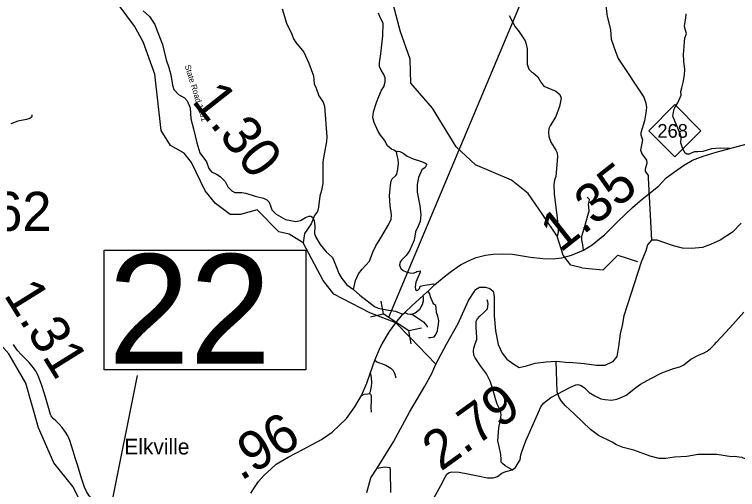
# Model space of a CAD drawing. Extents: x 1248089 to 1457196, y 820910 to 988753.
# Drawn here: x 1288997 to 1298239, y 853327 to 859401 of the extents above; entities that cross this region are included whole.
import ezdxf

# ---------------------------------------------------------------- set-up
doc = ezdxf.new("R2010")
doc.units = 0
for name, color, linetype in [('Exist Civil Demographics Community Label', 7, 'Continuous'), ('Exist Hydrographic Creek Single Shore', 7, 'Continuous'), ('Exist Hydrographic Misc Water Feature', 7, 'Continuous'), ('Exist Hydrographic River Shore', 7, 'Continuous'), ('Exist Road Non-System Type 51', 7, 'Continuous'), ('Exist Road Primary NC Attributed', 7, 'Continuous'), ('Exist Road Primary NC Shield CELL', 7, 'Continuous'), ('Exist Road Primary NC Shield Number Label', 7, 'Continuous'), ('Exist Road Primary NC Structure Culvert CELL', 7, 'Continuous'), ('Exist Road Primary NC Structure Culvert Number Label', 7, 'Continuous'), ('Exist Road Primary NC Structure Standard Bridge Number Label', 7, 'Continuous'), ('Exist Road Secondary Type 10 Attributed', 7, 'Continuous'), ('Exist Road Secondary Type 51 Attributed', 7, 'Continuous'), ('Exist Road Secondary Type 51 Label', 7, 'Continuous'), ('Prop CMT Slope Fill', 7, 'Continuous'), ('Prop GRAU CAT1 Cell', 7, 'Continuous'), ('Prop Lane Lines', 7, 'Continuous')]:
    doc.layers.add(name, color=color, linetype=linetype)

msp = doc.modelspace()

# ---------------------------------------------------------------- linework, layer by layer
at = {"layer": 'Exist Hydrographic Creek Single Shore'}
for points in [[(1293871.9, 855459.9), (1293539.5, 855586.9), (1293076.8, 855824.7), (1292941.6, 856000.6), (1292687.3, 856482.3), (1292507.4, 856594.2), (1292374.3, 856623.2), (1292097.4, 856904.5), (1291887.3, 856843), (1291754.3, 856845.7), (1291565.4, 856984.1), (1291436.3, 857147.5), (1291261.3, 857508.8), (1291164.3, 857629), (1290992.2, 857724.4), (1290871.2, 857917.2), (1290789.2, 858637.8), (1290641.3, 859051.1), (1290529.2, 859253.6), (1290335.2, 859516.8)], [(1290064.4, 852792.6), (1290015.4, 852887.3), (1289862.9, 853130), (1289742.3, 853366.9), (1289499.3, 853667.3), (1289302.3, 854114.4), (1289141.3, 854685.5), (1288925.3, 855064.1), (1288789.3, 855212.9), (1288651.5, 855179.3), (1288449.3, 855034.3), (1288244.3, 854838.1), (1288177.3, 854806.7), (1288102.3, 854818), (1287963.3, 854945.5), (1287810.2, 855175.1), (1287422.3, 855983.9), (1287286.2, 856564.4), (1287261.2, 856581.3), (1287171.2, 856993.4), (1286998.2, 857062.6), (1286909.2, 857172.7), (1286855.2, 857341.2), (1286814.2, 857384.7)], [(1294384.6, 854929.6), (1294053.9, 855270.9), (1293871.9, 855459.9)]]:
    msp.add_lwpolyline(points, dxfattribs=at)
at = {"layer": 'Exist Hydrographic Misc Water Feature'}
for points in [[(1296249.4, 856161.3), (1296108.4, 856197), (1296011.4, 856323.7), (1295933.4, 856568.2), (1295748.4, 856841.1), (1295563.4, 857110.7), (1295350.4, 857282.4), (1294888.3, 857478.8), (1294644.3, 857710.2), (1294339.3, 858202.1), (1294063.3, 858522.8), (1294054.3, 858831.6), (1293929.3, 859178.8), (1293838.3, 859531.8), (1293751.3, 859740.4)], [(1296542.7, 859616.6), (1296574.8, 859375.5), (1296614.8, 859210.6), (1296625.7, 859086.4), (1296677.9, 858928.6), (1296713.6, 858837.6), (1297039.9, 858343.6), (1297068, 858266.7), (1297074.6, 858210.7), (1297068.9, 858142.8), (1297050.4, 858043), (1297004.6, 857888), (1297003.9, 857860.1), (1297022.4, 857799.8), (1296997.1, 857664.1), (1297016.1, 857619.4), (1297074, 857537.8), (1297081.2, 857498.3), (1297057.3, 857422.4), (1297056.7, 857398.6), (1297095.2, 857341.2), (1297098.6, 857313.3), (1297140.1, 856517.1)], [(1292420.4, 859472), (1292475.8, 859287.8), (1292542.6, 859150.3), (1292565, 859089.9), (1292591.9, 859040.9), (1292694.9, 858918.2), (1292759.5, 858779.1), (1292817.6, 858617), (1292827.1, 858512.6), (1292853.8, 858460.4), (1292889.3, 858359.6), (1292943.4, 858278), (1292958.2, 858229.3), (1292988.6, 857834.8), (1292987.1, 857778.2), (1292950.6, 857595.1), (1292938.6, 857513.3), (1292938, 857239.2), (1292919.8, 857150.1), (1292897.9, 857078.3), (1292884.5, 856938.2), (1292871.1, 856882.7), (1292833.8, 856831.7), (1292791.2, 856724.3), (1292702, 856598.8), (1292687.3, 856482.3)], [(1295318.2, 859386.8), (1295394.7, 859244), (1295449.2, 859178.9), (1295524.4, 859065), (1295539.3, 859020.4), (1295550, 858960.3), (1295551.2, 858766.5), (1295573.5, 858701.3), (1295608.7, 858664.5), (1295628.5, 858656.7), (1295687.2, 858603), (1295723.5, 858534.1), (1295762.4, 858484.9), (1295916.9, 858419.4), (1295967.9, 858377.4), (1295982.7, 858329.5), (1295962.1, 858225.7), (1295915, 858098.6), (1295844, 857976.9), (1295829.1, 857941.1), (1295823.9, 857892.8), (1295826.7, 857841), (1295852.8, 857768.3), (1295916.5, 857666.9), (1295931.6, 857630.5), (1295938.4, 857581.9), (1295918.1, 857330.4), (1295901, 857282.3), (1295891.7, 857226.7), (1295896.6, 857102.6), (1295928, 856833.7), (1295944.8, 856669.6), (1295946.3, 856615.4), (1295933.4, 856568.2)], [(1296249.4, 856161.3), (1296520.5, 856135.9), (1296708.7, 856324.2), (1296959.5, 856242.3)], [(1298204, 853751.5), (1298163.8, 853746.5), (1297976.4, 853773.3), (1297736.1, 853773.2), (1297591.6, 853749), (1297435.2, 853742.2), (1297322.7, 853725.6), (1297238.7, 853725.7), (1297123.3, 853752.6), (1296913, 853831.5), (1296777.7, 853863), (1296692.4, 853896.7), (1296637.3, 853932.2), (1296463.4, 854017), (1296361.1, 854092.9), (1296152, 854296.6), (1296038.3, 854395.6), (1295990.5, 854455.7), (1295960.6, 854501.9), (1295933.4, 854578), (1295922.1, 854966.3)], [(1298651.7, 853526), (1298588.6, 853569.4), (1298533.4, 853600.7), (1298486.3, 853643.8), (1298415.2, 853679.5), (1298383.6, 853700.2), (1298296.3, 853738.2), (1298256, 853739.4), (1298204, 853751.5)], [(1293632.2, 853600), (1293730.5, 853618), (1293793.5, 853610.1), (1293800.4, 853561.6), (1293803.6, 853289.1)]]:
    msp.add_lwpolyline(points, dxfattribs=at)
at = {"layer": 'Exist Hydrographic River Shore'}
for points in [[(1298284.5, 856731), (1298172.8, 856618.1), (1298016.7, 856517.1), (1297892.8, 856462), (1297791.8, 856420.6), (1297649.6, 856406.8), (1297534.8, 856411.4), (1297420.1, 856443.6), (1297296.1, 856484.9), (1297213.5, 856517.1), (1297140.1, 856517.1), (1297089.6, 856457.4), (1297066.7, 856379.3), (1297007, 856232.3), (1296786.7, 855547.9), (1296763.7, 855423.9), (1296740.8, 855318.3), (1296717.8, 855157.5), (1296694.9, 855028.9), (1296639.8, 854960), (1296543.4, 854914.1), (1296437.9, 854914.1), (1296277.2, 854932.5), (1296089, 854950.8)], [(1294384.6, 854929.6), (1294517.7, 855186.8), (1294669.1, 855448.6), (1294802.2, 855742.6), (1294871.1, 855852.8), (1294889.4, 855885), (1294939.9, 855912.5), (1295017.9, 855912.5), (1295073, 855898.7), (1295114.3, 855862), (1295128.1, 855793.1), (1295128.1, 855687.5), (1295128.1, 855549.7), (1295146.5, 855356.8), (1295178.6, 855182.2), (1295229.1, 855072), (1295288.7, 854993.9), (1295380.5, 854929.6), (1295449.4, 854888.3), (1295541.2, 854906.6), (1295651.3, 854943.4), (1295793.6, 854961.7), (1295922.1, 854966.3), (1296089, 854950.8)], [(1293499.6, 853289.6), (1293550.1, 853477.9), (1293632.2, 853600), (1293843.3, 853935.3), (1294045.3, 854316.5), (1294242.7, 854647.2), (1294329.5, 854810.2), (1294384.6, 854929.6)]]:
    msp.add_lwpolyline(points, dxfattribs=at)
at = {"layer": 'Exist Road Non-System Type 51'}
for points in [[(1293878.7, 857645.1), (1293845.2, 857666.3), (1293815.2, 857678.7), (1293764, 857722.8), (1293730.4, 857786.4), (1293714.5, 857811.1), (1293677.5, 857857.1), (1293645.7, 857903), (1293592.8, 858017.8), (1293576.9, 858083.2), (1293587.5, 858157.4), (1293626.4, 858276), (1293654.6, 858353.8), (1293689.9, 858433.3), (1293716.4, 858473.9), (1293735.8, 858539.2), (1293734, 858592.2), (1293719.9, 858634.6), (1293682.9, 858689.4), (1293661.7, 858735.3), (1293661.7, 858781.2), (1293677.6, 858897.8), (1293704, 859129.2), (1293711.1, 859288.8), (1293675.8, 859354.2), (1293649.2, 859415.7)], [(1298141.3, 857687.4), (1298017.4, 857691), (1297906.2, 857684), (1297849.7, 857664.5), (1297796.7, 857648.6), (1297733.2, 857645.1), (1297687.3, 857645.1), (1297653.8, 857632.7), (1297620.2, 857613.3), (1297592, 857616.8), (1297569.1, 857627.4), (1297553.2, 857657.5), (1297532, 857708.7), (1297516.1, 857758.1), (1297517.9, 857825.3), (1297510.8, 857865.9), (1297484.3, 857924.2), (1297413.7, 858099.1), (1297419, 858152), (1297431.4, 858205), (1297475.5, 858272.2), (1297518.1, 858367.9), (1297516.3, 858415.6), (1297526.9, 858465), (1297546.3, 858530.4), (1297562.2, 858629.3), (1297567.5, 858696.4), (1297551.6, 858802.4), (1297548.1, 858889), (1297556.9, 858989.6), (1297562.2, 859049.7), (1297564, 859097.4), (1297585.1, 859158.2), (1297569.2, 859211.1), (1297562.2, 859255.3), (1297571, 859308.3), (1297576.3, 859354.2), (1297583.4, 859410.7)], [(1289216.6, 858118.8), (1289219.5, 858098.3), (1289213.7, 858086.6), (1289193.2, 858069), (1289149.3, 858060.2), (1289041.1, 858036.8), (1288950.4, 858001.7)], [(1293331.5, 855886.2), (1293354.8, 855997.7), (1293395.3, 856084.3), (1293443, 856146.1), (1293488.9, 856193.8), (1293533, 856246.8), (1293578.9, 856363.3), (1293617.7, 856442.8), (1293693.6, 856568.2), (1293771.3, 856700.7), (1293811.7, 856779.2), (1293817, 856839.2), (1293801.1, 856955.8), (1293790.5, 857088.3), (1293804.6, 857213.7), (1293811.7, 857273.7), (1293825.8, 857300.2), (1293864.6, 857335.6), (1293871.7, 857340.9), (1293885.8, 857358.5), (1293898.2, 857422.1), (1293903.5, 857496.3), (1293901.6, 857548), (1293889.3, 857599.2), (1293878.7, 857645.1)], [(1293878.7, 857645.1), (1293892.3, 857652.9), (1293924, 857651.2), (1293966.4, 857626.4), (1294015.8, 857591.1), (1294093.5, 857555.8), (1294185.3, 857524), (1294243.5, 857506.3), (1294268.2, 857488.7), (1294245.3, 857442.7), (1294202.9, 857412.7), (1294160.5, 857315.6), (1294142.9, 857229), (1294142.9, 857128.3), (1294180, 856955.2), (1294190.6, 856838.6), (1294181.7, 856753), (1294158.8, 856694.7), (1294123.5, 856622.3), (1294104.1, 856516.3), (1294047.6, 856380.3), (1294003.9, 856321.3), (1293949.2, 856264.8), (1293926.2, 856236.5), (1293917.4, 856194.1), (1293933.3, 856153.5), (1293963.3, 856127), (1294005.6, 856109.3), (1294051.5, 856097), (1294092.1, 856095.2), (1294125.7, 856105.8), (1294141.6, 856116.4), (1294183.9, 856121.7), (1294180.4, 856105.8), (1294153.9, 856038.7), (1294127.4, 855976.9), (1294116.8, 855916.8), (1294122.1, 855885), (1294131, 855872.7), (1294152.1, 855878), (1294175.1, 855895.6), (1294183.9, 855927.4), (1294243.9, 855939.8), (1294303.9, 855948.6), (1294344.5, 855957.4), (1294370, 855949.3)], [(1296269.1, 856389), (1296261, 856455.1), (1296250.4, 856518.7), (1296246.9, 856566.4), (1296282.2, 856677.6), (1296326.3, 856831.3), (1296342.2, 856889.6), (1296338.7, 856939.1), (1296335.1, 856975.2), (1296344, 857010.5), (1296347.5, 857033.5), (1296329.9, 857051.1), (1296315.7, 857067)], [(1294079.7, 855568.1), (1294120.3, 855587.6), (1294176.8, 855635.3), (1294213.9, 855691.8), (1294224.5, 855741.3), (1294226.2, 855776.6), (1294222.7, 855806.6)], [(1294289.8, 855271.4), (1294319.8, 855269.6), (1294360.4, 855280.2), (1294379.8, 855301.4), (1294402.8, 855354.4), (1294409.8, 855389.7), (1294418.6, 855437.4), (1294420.4, 855485.1), (1294406.3, 855543.4), (1294390.4, 855591.1), (1294386.9, 855651.2), (1294381.6, 855679.4), (1294358.6, 855695.3), (1294342.7, 855720.1), (1294314.5, 855790.7), (1294305.7, 855827.8), (1294284.5, 855863.1)], [(1295357.1, 853580), (1295267.7, 853631.3), (1295233, 853661.9), (1295216.7, 853678.3), (1295216.7, 853717), (1295212.6, 853774.2), (1295190.2, 853876.3), (1295173.9, 853951.8), (1295178, 854006.9), (1295186.1, 854115.1), (1295204.5, 854196.8), (1295216.8, 854281.2), (1295208.6, 854332.2), (1295184.1, 854385.3), (1295167.8, 854417.9), (1295149.5, 854473), (1295131.1, 854532.2), (1295108.7, 854624.1), (1295078.1, 854711.9), (1295029.1, 854807.8), (1294953.6, 854907.9), (1294886.3, 855009.9), (1294870.3, 855043.8), (1294862.1, 855101), (1294868.2, 855133.6), (1294884.5, 855190.8), (1294904.9, 855243.9), (1294907, 855272.4), (1294898.8, 855401), (1294898.8, 855478.6), (1294917.2, 855508.5), (1294943.7, 855543.2), (1294996.7, 855590.1), (1295041.6, 855639.1), (1295053.8, 855702.4), (1295047.7, 855728.9), (1295039.5, 855751.4)], [(1293988, 855589.3), (1294021.5, 855571.7), (1294055, 855568.1), (1294079.7, 855568.1)], [(1294079.7, 855568.1), (1294136.2, 855529.3), (1294224.5, 855469.2), (1294265.1, 855425.1), (1294275.7, 855402.1)], [(1293601.9, 854981.7), (1293630.2, 854960.2), (1293743.2, 854916.1), (1293806.7, 854879), (1293838.5, 854850.7), (1293859.6, 854803), (1293872, 854755.4)], [(1293536.7, 854554.5), (1293549.1, 854581), (1293561.4, 854642.9), (1293563.2, 854695.8), (1293559.7, 854761.2), (1293546.9, 854824.5)], [(1293430.7, 854529.9), (1293467.9, 854547.5), (1293512, 854552.8), (1293536.7, 854554.5), (1293547.3, 854547.5), (1293557.9, 854528), (1293557.9, 854473.3), (1293552.6, 854374.4), (1293554.4, 854314.3)]]:
    msp.add_lwpolyline(points, dxfattribs=at)
at = {"layer": 'Exist Road Primary NC Attributed'}
for points in [[(1293962.5, 855567.8), (1293988, 855589.3), (1294077.2, 855676.8), (1294222.7, 855806.6), (1294267.5, 855852.3), (1294284.5, 855863.1), (1294370, 855949.3), (1294509.9, 856065), (1294584.5, 856121), (1294695.9, 856198.6), (1294800.3, 856252.7), (1294899.1, 856293.8), (1295016.6, 856321.8), (1295113.6, 856334.9), (1295238.6, 856340.5), (1295361.7, 856334.9), (1295593.9, 856299.4), (1295750.6, 856278.9), (1295881.1, 856277), (1295994.9, 856290.1), (1296118, 856321.8), (1296269.1, 856389), (1296380, 856457.1), (1296544.1, 856585.9), (1296713.8, 856757.6), (1296898.4, 856935), (1296994.8, 857019.9), (1297231.7, 857212.2), (1297328.7, 857311.1), (1297462.9, 857410), (1297548.7, 857471.6), (1297662, 857538.1), (1297801.9, 857590.4), (1297964.1, 857642.6), (1298141.3, 857687.4), (1298362.8, 857748.7)], [(1292018.9, 853279.7), (1292073, 853365.5), (1292118.1, 853431), (1292190.3, 853512.2), (1292273.8, 853589), (1292343.7, 853649.9), (1292493.1, 853741.2), (1292692.8, 853842.8), (1292919.5, 853965.9), (1293057.7, 854061.1), (1293239.3, 854237.2), (1293348.7, 854386.2), (1293430.7, 854529.9), (1293499.5, 854687.9), (1293546.9, 854824.5), (1293601.9, 854981.7), (1293674.1, 855153.2), (1293696.6, 855189.1), (1293788.4, 855349.1), (1293871.9, 855459.9), (1293962.5, 855567.8)]]:
    msp.add_lwpolyline(points, dxfattribs=at)
at = {"layer": 'Exist Road Primary NC Shield CELL'}
msp.add_lwpolyline([(1297105, 857915.1), (1297438, 858248.1), (1297771, 857915.1), (1297438, 857582.1)], close=True, dxfattribs=at)
at = {"layer": 'Exist Road Primary NC Structure Culvert CELL'}
for p, q in [((1293679.3, 855737.2), (1293708.2, 855573.2)), ((1293545.9, 855535.5), (1293708.2, 855573.2)), ((1294039.1, 855354.3), (1293708.2, 855573.2)), ((1294201.3, 855392), (1294039.1, 855354.3)), ((1294067.9, 855190.3), (1294039.1, 855354.3))]:
    msp.add_line(p, q, dxfattribs=at)
at = {"layer": 'Exist Road Primary NC Structure Culvert Number Label'}
msp.add_line((1293782.7, 855529.8), (1296134.5, 861133.4), dxfattribs=at)
at = {"layer": 'Exist Road Primary NC Structure Standard Bridge Number Label'}
msp.add_line((1290205.7, 852980), (1290569.1, 854783), dxfattribs=at)
msp.add_lwpolyline([(1290144.9, 856387.1), (1292721.4, 856387.1), (1292721.4, 854857.9), (1290144.9, 854857.9)], close=True, dxfattribs=at)
at = {"layer": 'Exist Road Secondary Type 10 Attributed'}
msp.add_lwpolyline([(1290640.7, 859449.5), (1290721.9, 859375), (1290789.6, 859273.4), (1290821.2, 859189.9), (1290888.8, 859016.1), (1290933.9, 858819.7), (1290970, 858722.6), (1290997.1, 858630), (1291017.3, 858495.9), (1291033.1, 858441.7), (1291091.8, 858378.5), (1291168.5, 858333.3), (1291204.6, 858294.9), (1291242.9, 858206.9), (1291249.7, 858066.9), (1291285.8, 857938.3), (1291328.1, 857759.6), (1291366.4, 857633.2), (1291449.9, 857515.8), (1291479.2, 857430), (1291513.1, 857387.1), (1291580.7, 857360), (1291628.1, 857328.4), (1291691.3, 857267.5), (1291722.8, 857197.5), (1291777, 857145.6), (1291813.1, 857125.2), (1291901, 857125.2), (1291955.2, 857116.2), (1292073.5, 857079.1), (1292181.8, 857052), (1292224.6, 857029.4), (1292251.7, 857000.1), (1292274.2, 856943.6), (1292287.8, 856903), (1292339.7, 856848.8), (1292459.2, 856778.8), (1292529.1, 856765.3), (1292594.6, 856754), (1292653.2, 856765.3), (1292718.6, 856805.9), (1292759.2, 856824), (1292784.1, 856824), (1292806.6, 856810.4), (1292826.9, 856763), (1292835.9, 856697.5), (1292833.7, 856600.5), (1292849.5, 856553.1), (1292903.6, 856460.5), (1292980.3, 856367.9), (1293063.8, 856293.4), (1293076.6, 856265.5), (1293117.2, 856159.4), (1293142, 856087.2), (1293180.4, 856026.2), (1293245.8, 855944.9), (1293331.5, 855886.2), (1293410.4, 855814), (1293597.7, 855667.3), (1293645, 855646.9), (1293778.1, 855622.1), (1293868.4, 855606.3), (1293897.7, 855595), (1293962.5, 855567.8)], dxfattribs=at)
at = {"layer": 'Exist Road Secondary Type 51 Attributed'}
for points in [[(1294309.6, 853129.8), (1294447.7, 853380.6), (1294502, 853483.3), (1294524.1, 853523.6), (1294554.3, 853545.8), (1294586.5, 853551.8), (1294679.1, 853547.8), (1294793.7, 853529.6), (1294920.5, 853503.5), (1295041.2, 853477.3), (1295113.6, 853475.3), (1295133.8, 853479.3), (1295170, 853493.4), (1295224.3, 853535.7), (1295278.6, 853557.8), (1295357.1, 853580), (1295399.3, 853608.2), (1295429.5, 853658.5), (1295459.7, 853706.8), (1295467.7, 853771.3), (1295487.9, 853823.6), (1295531.8, 853949.2), (1295664.6, 854247.2), (1295725, 854384.1), (1295757.1, 854430.4), (1295852.6, 854502.6), (1296106.1, 854637.5), (1296172.5, 854667.7), (1296198.6, 854669.7), (1296238.9, 854657.6), (1296283.1, 854629.4), (1296343.5, 854567), (1296413.9, 854524.7), (1296492.4, 854486.5), (1296548.7, 854478.4), (1296629.2, 854470.4), (1296695.6, 854484.5), (1296751.9, 854504.6), (1296816.3, 854532.8), (1296872.6, 854577.1), (1296939, 854633.5), (1296997.4, 854673.7), (1297130.8, 854748.9), (1297271.6, 854817.4), (1297420.5, 854875.8), (1297503, 854897.9), (1297551.3, 854920.1), (1297643.8, 854992.6), (1297738.4, 855046.9), (1297812.9, 855075.1), (1297851.1, 855097.3), (1297895.3, 855129.5), (1297943.6, 855181.8), (1297971.8, 855210), (1298142.2, 855395.8), (1298319.3, 855595.1)], [(1289874.8, 853410.1), (1289852, 853474.6), (1289821.9, 853569.3), (1289801.4, 853641.7), (1289774.9, 853718.3), (1289746.8, 853816.9), (1289724.2, 853885.4), (1289703.6, 853955.9), (1289678.7, 854014.4), (1289649.6, 854059), (1289604.8, 854119.9), (1289567.7, 854164.7), (1289526.4, 854203.5), (1289493, 854234.2), (1289473.5, 854256.6), (1289463.7, 854270.8), (1289458, 854285), (1289450.6, 854315.1), (1289437.5, 854361.4), (1289415, 854433.9), (1289396.2, 854496.3), (1289371.8, 854576.9), (1289349.2, 854645.4), (1289328.4, 854705.8), (1289309.5, 854760.2), (1289294.1, 854792.5), (1289269, 854839.1), (1289257.4, 854859.3), (1289241.8, 854881.6), (1289220.4, 854910.1), (1289185.2, 854950.8), (1289132.2, 855003.9), (1289085.1, 855048.9), (1289032.3, 855110), (1289010.9, 855142.4), (1288985.7, 855183)], [(1290301.6, 852872.1), (1290167.3, 853024.2), (1290132, 853064.7), (1290084.9, 853109.7), (1290037.8, 853156.7), (1289996.7, 853201.5), (1289951.6, 853248.5), (1289918.6, 853303.2), (1289891.7, 853357.7), (1289874.8, 853410.1)]]:
    msp.add_lwpolyline(points, dxfattribs=at)

# ---------------------------------------------------------------- texts
at = {"layer": 'Exist Civil Demographics Community Label'}
msp.add_text('Elkville', height=200, dxfattribs=at).set_placement((1290401.3, 853775.4))
at = {"layer": 'Exist Road Primary NC Shield Number Label'}
msp.add_text('268', height=175, dxfattribs=at).set_placement((1297214.1, 857825.4))
at = {"layer": 'Exist Road Primary NC Structure Standard Bridge Number Label'}
msp.add_text('22', height=1400, dxfattribs=at).set_placement((1290195, 854937))
at = {"layer": 'Exist Road Secondary Type 51 Label'}
msp.add_text('State Road 1161', height=75, rotation=287.02717, dxfattribs=at).set_placement((1291172.2, 858745.2))
at = {"layer": 'Prop CMT Slope Fill'}
for s, rotation, p in [('1.35', 38.28587, (1295972.3, 856346.4)), ('.96', 31.41902, (1291890, 853431.2))]:
    msp.add_text(s, height=500, rotation=rotation, dxfattribs=at).set_placement(p)
at = {"layer": 'Prop GRAU CAT1 Cell'}
for s, rotation, p in [('1.30', 308.26781, (1291253.5, 858292.1)), ('1.31', 301.88311, (1288852.1, 855816.9)), ('2.79', 35.88603, (1294446.4, 853552.5))]:
    msp.add_text(s, height=500, rotation=rotation, dxfattribs=at).set_placement(p)
at = {"layer": 'Prop Lane Lines'}
msp.add_text('1162', height=500, dxfattribs=at).set_placement((1287982.3, 856633.8))

doc.saveas('drawing.dxf')
